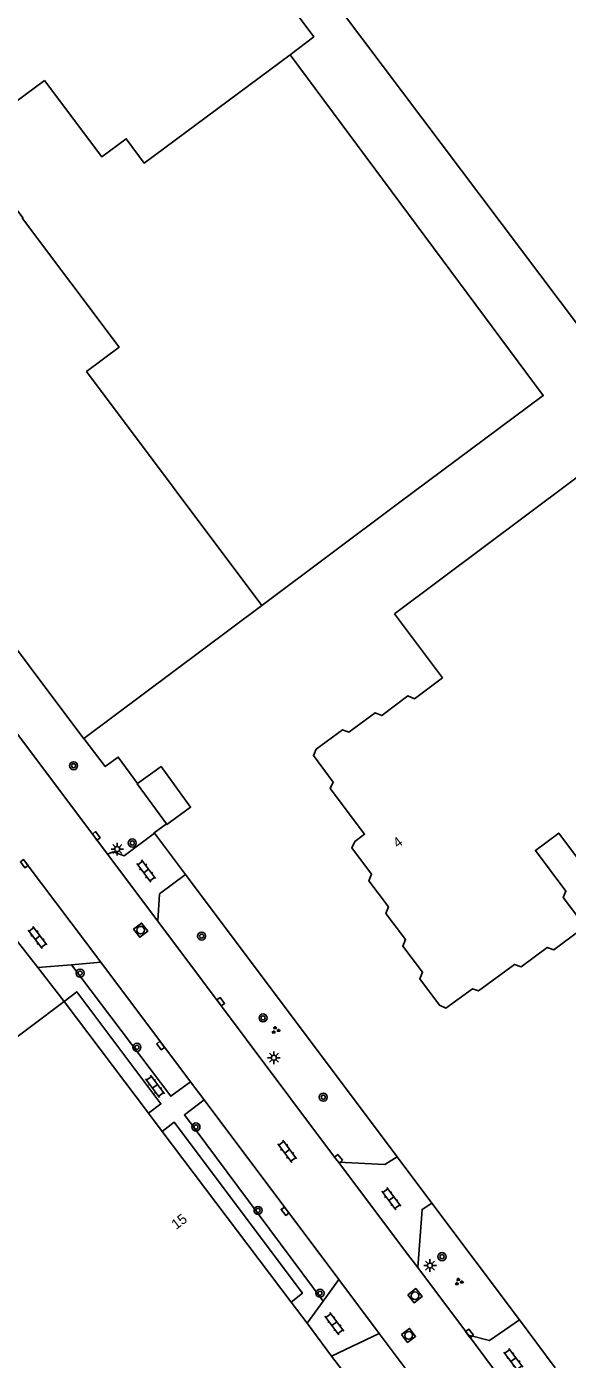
# Model space of a CAD drawing. Extents: x 130998 to 133001, y 398999 to 403002.
# Drawn here: x 131716.6 to 131770.1, y 400245.1 to 400377.1 of the extents above; entities that cross this region are included whole.
import ezdxf

# ---------------------------------------------------------------- set-up
doc = ezdxf.new("R2010")
doc.units = 0
for name, color, linetype in [('gg-afsc-hekwerk', 7, 'Continuous'), ('gg-anno-huisnummerreeks BGT', 7, 'Continuous'), ('gg-bbg-bijgebouw', 7, 'Continuous'), ('gg-bbg-gedigitaliseerde bebouwing', 7, 'Continuous'), ('gg-bbg-hoofdgebouw', 7, 'Continuous'), ('gg-bbg-tussenscheiding', 7, 'Continuous'), ('gg-knt-verharding', 7, 'Continuous'), ('gg-knt-verharding nz', 7, 'Continuous'), ('gt-grn-weggrens', 7, 'Continuous'), ('gt-symb-boom', 7, 'Continuous'), ('gt-symb-groenvak', 7, 'Continuous'), ('gt-symb-klinker verharding', 7, 'Continuous'), ('gt-symb-kolk', 7, 'Continuous'), ('gt-symb-lichtmast', 7, 'Continuous'), ('gt-symb-rioolschacht', 7, 'Continuous')]:
    doc.layers.add(name, color=color, linetype=linetype)

# ---------------------------------------------------------------- blocks, each defined once
blk = doc.blocks.new('gt0-GRVAK')
at = {"layer": 'gt-symb-groenvak'}
for p, q in [((-0.11, 0.19), (-0.23, 0.24)), ((-0.18, 0.15), (0.09, 0.15)), ((-0.09, 0.21), (-0.16, 0.32)), ((-0.05, 0.21), (-0.05, 0.39)), ((0, 0.21), (0.06, 0.32)), ((0.01, 0.19), (0.13, 0.24)), ((0.26, -0.05), (0.2, 0.06)), ((0.3, -0.05), (0.3, 0.13)), ((0.35, -0.05), (0.41, 0.06)), ((-0.24, -0.23), (-0.36, -0.18)), ((-0.32, -0.26), (-0.05, -0.26)), ((-0.23, -0.21), (-0.29, -0.09)), ((-0.18, -0.2), (-0.18, -0.02)), ((-0.14, -0.21), (-0.07, -0.09)), ((-0.12, -0.23), (0, -0.18)), ((0.24, -0.07), (0.12, -0.02)), ((0.17, -0.11), (0.44, -0.11)), ((0.37, -0.07), (0.49, -0.02))]:
    blk.add_line(p, q, dxfattribs=at)
blk = doc.blocks.new('gt0-KOLK')
at = {"layer": 'gt-symb-kolk'}
blk.add_lwpolyline([(0, 0), (0.37, 0), (0.37, 0.4), (-0.38, 0.4), (-0.38, 0), (0, 0)], dxfattribs=at)
blk = doc.blocks.new('gt0-KL1')
at = {"layer": 'gt-symb-klinker verharding'}
for p, q in [((-1.15, 0.3), (1.15, 0.3)), ((-1, -0.3), (-1, 0.3)), ((-0.5, 0.3), (-0.5, 0.45)), ((0, -0.3), (0, 0.3)), ((0.5, 0.3), (0.5, 0.45)), ((1, -0.3), (1, 0.3)), ((-1.15, -0.3), (1.15, -0.3)), ((-0.5, -0.45), (-0.5, -0.3)), ((0.5, -0.45), (0.5, -0.3))]:
    blk.add_line(p, q, dxfattribs=at)
blk = doc.blocks.new('gt0-RS')
at = {"layer": 'gt-symb-rioolschacht'}
blk.add_lwpolyline([(-0.5, -0.5), (0.5, -0.5), (0.5, 0.5), (-0.5, 0.5)], close=True, dxfattribs=at)
blk.add_circle((0, 0), 0.375, dxfattribs=at)
blk = doc.blocks.new('gt0-LMAST')
at = {"layer": 'gt-symb-lichtmast'}
for p, q in [((-0.18, 0.17), (-0.45, 0.44)), ((-0.01, 0.25), (-0.01, 0.62)), ((0.17, 0.17), (0.44, 0.44)), ((-0.26, 0), (-0.63, 0)), ((-0.18, -0.18), (-0.45, -0.45)), ((-0.01, -0.25), (-0.01, -0.63)), ((0.44, -0.45), (0.17, -0.18)), ((0.24, 0), (0.62, 0))]:
    blk.add_line(p, q, dxfattribs=at)
blk.add_circle((-0.01, 0), 0.25, dxfattribs=at)
blk = doc.blocks.new('gt0-BOOM')
at = {"layer": 'gt-symb-boom'}
for radius in [0.4, 0.2]:
    blk.add_circle((0, 0), radius, dxfattribs=at)

msp = doc.modelspace()

# ---------------------------------------------------------------- linework, layer by layer
at = {"layer": 'gg-afsc-hekwerk'}
for p, q in [((131732.33, 400293.11), (131729.24, 400297.22)), ((131753.29, 400265.15), (131732.33, 400293.11)), ((131756.71, 400260.59), (131753.29, 400265.15)), ((131765.39, 400249.02), (131756.71, 400260.59)), ((131768.95, 400244.26), (131765.39, 400249.02))]:
    msp.add_line(p, q, dxfattribs=at)
for points in [[(131722.27, 400306.59), (131724.37, 400303.8), (131725.67, 400304.75), (131727.57, 400302.12)], [(131729.24, 400297.22), (131729.22, 400297.25), (131730.43, 400298.14)]]:
    msp.add_lwpolyline(points, dxfattribs=at)
at = {"layer": 'gg-bbg-bijgebouw'}
for points in [[(131727.57, 400302.12), (131729.9, 400303.81), (131732.83, 400299.78), (131730.48, 400298.07), (131730.43, 400298.14)], [(131727.57, 400302.12), (131727.54, 400302.1), (131730.43, 400298.14)]]:
    msp.add_lwpolyline(points, dxfattribs=at)
at = {"layer": 'gg-bbg-gedigitaliseerde bebouwing'}
msp.add_line((131722.27, 400306.59), (131739.88, 400319.77), dxfattribs=at)
for points in [[(131738.01, 400391.6), (131773.35, 400344.65), (131805.3, 400368.71), (131774.77, 400409.26)], [(131739.88, 400319.77), (131753.42, 400329.9), (131767.76, 400340.55), (131742.68, 400374.3)], [(131753.03, 400318.94), (131801.13, 400354.92), (131830.03, 400316.28), (131781.94, 400280.32)]]:
    msp.add_lwpolyline(points, dxfattribs=at)
at = {"layer": 'gg-bbg-hoofdgebouw'}
for p, q in [((131640.39, 400220.67), (131720.31, 400280.55)), ((131720.31, 400280.55), (131728.66, 400269.48)), ((131728.66, 400269.48), (131730.02, 400267.68)), ((131730.02, 400267.68), (131742.78, 400250.78)), ((131742.78, 400250.78), (131744.36, 400248.68)), ((131744.36, 400248.68), (131746.8, 400245.44)), ((131746.8, 400245.44), (131749.28, 400242.16))]:
    msp.add_line(p, q, dxfattribs=at)
for points in [[(131718.36, 400371.75), (131724.05, 400364.18), (131726.46, 400365.97), (131728.24, 400363.57), (131742.68, 400374.3)], [(131718.36, 400371.75), (131714.54, 400368.92), (131713.87, 400369.8), (131711.29, 400367.87), (131711.95, 400366.99), (131708.3, 400364.23)], [(131722.27, 400306.59), (131722.24, 400306.57), (131695.25, 400342.57), (131695.34, 400342.64)], [(131771.43, 400287.6), (131768.81, 400285.65), (131768.15, 400285.9), (131765.57, 400283.98), (131764.92, 400284.21), (131761.36, 400281.59), (131760.76, 400281.8), (131758.1, 400279.9), (131757.47, 400280.18), (131755.53, 400282.8), (131755.8, 400283.44), (131753.85, 400286.03), (131754.12, 400286.67), (131752.17, 400289.27), (131752.43, 400289.91), (131750.49, 400292.51), (131750.75, 400293.14), (131748.8, 400295.75), (131749.1, 400296.39), (131750.06, 400297.11), (131746.66, 400301.64), (131746.94, 400302.28), (131744.99, 400304.89), (131745.27, 400305.53), (131747.89, 400307.46), (131748.51, 400307.2), (131751.12, 400309.13), (131751.77, 400308.86), (131754.34, 400310.81), (131755, 400310.53), (131757.77, 400312.61), (131753.03, 400318.94)], [(131781.94, 400280.32), (131769.3, 400297.22), (131766.98, 400295.5), (131770.01, 400291.47), (131769.73, 400290.84), (131771.7, 400288.22)]]:
    msp.add_lwpolyline(points, dxfattribs=at)
at = {"layer": 'gg-bbg-tussenscheiding'}
msp.add_lwpolyline([(131708.3, 400364.23), (131711.57, 400359.87), (131712.13, 400360.29), (131713.37, 400358.63), (131714.96, 400359.83), (131716.23, 400358.14), (131716.17, 400358.09), (131725.74, 400345.33), (131722.53, 400342.92), (131739.88, 400319.77)], dxfattribs=at)
at = {"layer": 'gg-knt-verharding'}
for p, q in [((131724.59, 400295.15), (131687.06, 400345.17)), ((131714.13, 400288.48), (131717.69, 400283.91)), ((131747.08, 400265.14), (131729.57, 400288.5)), ((131717.69, 400283.91), (131720.31, 400280.55)), ((131721.03, 400284.19), (131723.93, 400284.44)), ((131723.93, 400284.44), (131732.81, 400272.6)), ((131732.81, 400272.6), (131734.16, 400270.8)), ((131734.16, 400270.8), (131747.51, 400253.01)), ((131747.49, 400264.65), (131747.08, 400265.14)), ((131760.34, 400247.5), (131755.35, 400254.2)), ((131747.51, 400253.01), (131745.97, 400250.88)), ((131746.8, 400245.44), (131751.52, 400247.67)), ((131751.52, 400247.67), (131755.38, 400242.53))]:
    msp.add_line(p, q, dxfattribs=at)
for points in [[(131742.68, 400374.3), (131745.02, 400376.08), (131737.19, 400386.62)], [(131729.24, 400297.22), (131726.26, 400294.97), (131725.17, 400295.35), (131724.59, 400295.15)], [(131729.57, 400288.5), (131729.75, 400291.2), (131732.33, 400293.11)], [(131732.81, 400272.6), (131730.86, 400271.17), (131721.03, 400284.19)], [(131728.66, 400269.48), (131729.89, 400270.4), (131721.56, 400281.51), (131720.31, 400280.55)], [(131745.97, 400250.88), (131732.21, 400269.32), (131734.16, 400270.8)], [(131742.78, 400250.78), (131743.9, 400251.65), (131731.21, 400268.59), (131730.02, 400267.68)], [(131753.29, 400265.15), (131752.08, 400264.39), (131747.49, 400264.65)], [(131755.35, 400254.2), (131755.75, 400259.95), (131756.71, 400260.59)], [(131765.39, 400249.02), (131762.42, 400246.97), (131760.34, 400247.5)]]:
    msp.add_lwpolyline(points, dxfattribs=at)
at = {"layer": 'gg-knt-verharding nz'}
for p, q in [((131724.59, 400295.15), (131729.57, 400288.5)), ((131716.56, 400294.25), (131723.93, 400284.44)), ((131748.4, 400263.41), (131747.49, 400264.65)), ((131748.4, 400263.41), (131754.32, 400255.52)), ((131754.32, 400255.52), (131755.35, 400254.2)), ((131747.51, 400253.01), (131751.52, 400247.67)), ((131760.34, 400247.5), (131765.84, 400240.17))]:
    msp.add_line(p, q, dxfattribs=at)
at = {"layer": 'gt-grn-weggrens'}
for p, q in [((131721.03, 400284.19), (131717.69, 400283.91)), ((131744.36, 400248.68), (131745.97, 400250.88))]:
    msp.add_line(p, q, dxfattribs=at)

# ---------------------------------------------------------------- block references
at = {"layer": 'gt-symb-boom'}
for p in [(131721.24, 400303.89), (131727.05, 400296.24), (131733.92, 400287.02), (131721.89, 400283.35), (131740.01, 400278.92), (131727.51, 400276.01), (131745.97, 400271.07), (131733.36, 400268.12), (131739.51, 400259.86), (131757.73, 400255.28), (131745.65, 400251.66)]:
    msp.add_blockref('gt0-BOOM', p, dxfattribs=at)
at = {"layer": 'gt-symb-groenvak'}
for p in [(131741.24, 400277.71), (131759.39, 400252.79)]:
    msp.add_blockref('gt0-GRVAK', p, dxfattribs=at)
at = {"layer": 'gt-symb-klinker verharding'}
for p, rotation in [((131728.43, 400293.46), -53.130102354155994), ((131717.67, 400286.88), -53.130102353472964), ((131729.31, 400272.14), 127.0761203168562), ((131742.4, 400265.71), -53.130102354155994), ((131752.71, 400261.02), -53.130102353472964), ((131747.07, 400248.64), -53.13010235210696), ((131764.8, 400245.09), -53.130102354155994)]:
    msp.add_blockref('gt0-KL1', p, dxfattribs=dict(at, rotation=rotation))
at = {"layer": 'gt-symb-kolk'}
for p, rotation in [((131723.33, 400296.82), -53.33640753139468), ((131716.51, 400294.31), 126.9958977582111), ((131735.65, 400280.41), -53.29046597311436), ((131730.02, 400276.31), 126.66359246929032), ((131747.33, 400264.85), -50.561375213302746), ((131742.34, 400259.9), 126.78969964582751), ((131760.3, 400247.55), -53.00410224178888)]:
    msp.add_blockref('gt0-KOLK', p, dxfattribs=dict(at, rotation=rotation))
at = {"layer": 'gt-symb-lichtmast'}
for p in [(131725.58, 400295.64), (131741.09, 400274.98), (131756.55, 400254.4)]:
    msp.add_blockref('gt0-LMAST', p, dxfattribs=at)
at = {"layer": 'gt-symb-rioolschacht'}
for p, rotation in [((131727.88, 400287.61), -52.683025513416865), ((131755.05, 400251.41), -51.456537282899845), ((131754.42, 400247.48), -52.683025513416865)]:
    msp.add_blockref('gt0-RS', p, dxfattribs=dict(at, rotation=rotation))

# ---------------------------------------------------------------- texts
at = {"layer": 'gg-anno-huisnummerreeks BGT'}
for s, rotation, p in [('4', 36.8, (131753.34, 400295.7)), ('15', 37, (131731.4, 400257.92))]:
    msp.add_text(s, height=1, rotation=rotation, dxfattribs=at).set_placement(p)

doc.saveas('drawing.dxf')
